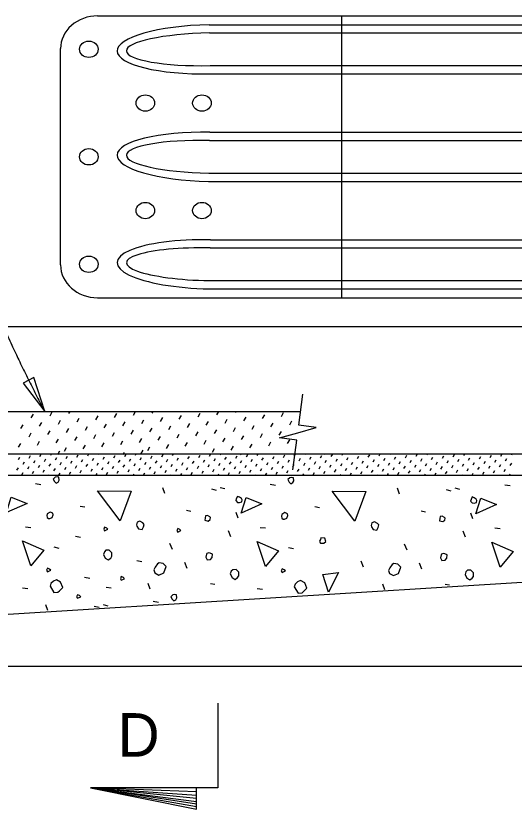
# Model space of a CAD drawing. Extents: x 1.5 to 68.7, y 0 to 31.1.
# Drawn here: x 28.438 to 31.375, y 8.892 to 13.565 of the extents above; entities that cross this region are included whole.
import ezdxf

# ---------------------------------------------------------------- set-up
doc = ezdxf.new("R2010")
doc.units = 0
for name, color, linetype in [('AdhocPoint_dp', 7, 'Continuous'), ('Border', 7, 'Continuous'), ('Patterning', 7, 'Continuous'), ('PlotBorder_dp', 7, 'Continuous'), ('SheetBorder_dp', 7, 'Continuous')]:
    doc.layers.add(name, color=color, linetype=linetype)

msp = doc.modelspace()

# ---------------------------------------------------------------- linework, layer by layer
at = {"layer": 'AdhocPoint_dp'}
for p, q in [((29.503, 8.9937), (28.878, 9.0171)), ((28.878, 9.0171), (29.503, 8.9737)), ((29.503, 8.9554), (28.878, 9.0171)), ((28.878, 9.0171), (29.503, 8.9371)), ((29.503, 8.9204), (28.878, 9.0171)), ((28.878, 9.0171), (29.503, 8.9071))]:
    msp.add_line(p, q, dxfattribs=at)
msp.add_lwpolyline([(28.6078, 11.2336), (28.5427, 11.4345), (28.4801, 11.4019)], close=True, dxfattribs=at)
for points in [[(30.0701, 10.8911), (30.0933, 11.0649), (29.9908, 11.0786), (30.0992, 11.1095), (30.2076, 11.1405), (30.1052, 11.1541), (30.1295, 11.3365)], [(29.628, 9.5171), (29.628, 9.0171), (28.878, 9.0171), (29.503, 8.8921), (29.503, 9.0171)]]:
    msp.add_lwpolyline(points, dxfattribs=at)
msp.add_open_spline([(25.4341, 13.3896), (27.814, 13.1117), (28.2987, 11.8257), (28.6078, 11.2336)], degree=2, dxfattribs=at)
at = {"layer": 'Border'}
for centre in [(28.8677, 13.3677), (29.201, 13.0511), (29.5344, 13.0511), (28.8677, 12.7345), (29.201, 12.418), (29.5344, 12.418), (28.8677, 12.1013)]:
    msp.add_ellipse(centre, major_axis=(0.0547, 0), ratio=0.882613, dxfattribs=at)
at = {"layer": 'Patterning'}
for p, q in [((28.9195, 13.5645), (37.6978, 13.5645)), ((30.3588, 11.9044), (30.3588, 13.5645)), ((29.5771, 13.5123), (37.6978, 13.5123)), ((29.5783, 13.4641), (37.6978, 13.4641)), ((28.7009, 12.0972), (28.7009, 13.3717)), ((29.5831, 13.2713), (37.6978, 13.2713)), ((29.5842, 13.2231), (37.6978, 13.2231)), ((29.5807, 12.8791), (37.6978, 12.8791)), ((29.5795, 12.8309), (37.6978, 12.8309)), ((29.5747, 12.6381), (37.6978, 12.6381)), ((29.5735, 12.5899), (37.6978, 12.5899)), ((29.5842, 12.246), (37.6978, 12.246)), ((29.5831, 12.1978), (37.6978, 12.1978)), ((29.5783, 12.0049), (37.6978, 12.0049)), ((29.5771, 11.9567), (37.6978, 11.9567)), ((28.9195, 11.9044), (37.6978, 11.9044)), ((28.5285, 11.1961), (28.5415, 11.2184)), ((28.6392, 11.209), (28.6521, 11.2314)), ((28.7498, 11.222), (28.757, 11.2345)), ((29.0199, 11.1991), (29.0329, 11.2215)), ((29.1305, 11.212), (29.1435, 11.2344)), ((29.2412, 11.225), (29.2467, 11.2345)), ((29.5113, 11.2021), (29.5242, 11.2245)), ((29.6219, 11.2151), (29.6332, 11.2345)), ((29.7325, 11.228), (29.7363, 11.2345)), ((29.892, 11.1921), (29.905, 11.2145)), ((30.0026, 11.2051), (30.0156, 11.2275)), ((28.5774, 11.1472), (28.5903, 11.1696)), ((28.688, 11.1602), (28.701, 11.1826)), ((28.7986, 11.1731), (28.8116, 11.1955)), ((28.9093, 11.1861), (28.9222, 11.2085)), ((29.0687, 11.1502), (29.0817, 11.1726)), ((29.1794, 11.1632), (29.1923, 11.1856)), ((29.29, 11.1762), (29.303, 11.1986)), ((29.4006, 11.1891), (29.4136, 11.2115)), ((29.5601, 11.1533), (29.5731, 11.1756)), ((29.6707, 11.1662), (29.6837, 11.1886)), ((29.7814, 11.1792), (29.7943, 11.2016)), ((30.0515, 11.1563), (30.0644, 11.1787)), ((28.4667, 11.1343), (28.4797, 11.1566)), ((28.6262, 11.0984), (28.6392, 11.1208)), ((28.7368, 11.1113), (28.7498, 11.1337)), ((28.8475, 11.1243), (28.8604, 11.1467)), ((28.9581, 11.1373), (28.9711, 11.1597)), ((29.1176, 11.1014), (29.1305, 11.1238)), ((29.2282, 11.1144), (29.2412, 11.1368)), ((29.3388, 11.1273), (29.3518, 11.1497)), ((29.4495, 11.1403), (29.4624, 11.1627)), ((29.6089, 11.1044), (29.6219, 11.1268)), ((29.7196, 11.1174), (29.7325, 11.1398)), ((29.8302, 11.1304), (29.8432, 11.1527)), ((29.9408, 11.1433), (29.9538, 11.1657)), ((28.5156, 11.0854), (28.5285, 11.1078)), ((28.7857, 11.0625), (28.7986, 11.0849)), ((28.8963, 11.0755), (28.9093, 11.0979)), ((29.0069, 11.0884), (29.0199, 11.1108)), ((29.1664, 11.0526), (29.1794, 11.075)), ((29.277, 11.0655), (29.29, 11.0879)), ((29.3877, 11.0785), (29.4006, 11.1009)), ((29.4983, 11.0915), (29.5113, 11.1139)), ((29.6578, 11.0556), (29.6707, 11.078)), ((29.7684, 11.0686), (29.7814, 11.0909)), ((29.879, 11.0815), (29.892, 11.1039)), ((29.9897, 11.0945), (30.0026, 11.1169)), ((28.4538, 11.0236), (28.4667, 11.046)), ((28.5644, 11.0366), (28.5774, 11.059)), ((28.675, 11.0495), (28.688, 11.0719)), ((28.8345, 11.0137), (28.8475, 11.0361)), ((28.9451, 11.0266), (28.9581, 11.049)), ((29.0558, 11.0396), (29.0687, 11.062)), ((29.3259, 11.0167), (29.3388, 11.0391)), ((29.4365, 11.0297), (29.4495, 11.0521)), ((29.5471, 11.0426), (29.5601, 11.065)), ((29.7066, 11.0068), (29.7196, 11.0291)), ((29.8172, 11.0197), (29.8302, 11.0421)), ((29.9279, 11.0327), (29.9408, 11.0551)), ((30.0385, 11.0456), (30.0515, 11.068)), ((28.5793, 10.9683), (28.5874, 10.9823)), ((28.6428, 10.9764), (28.6474, 10.9845)), ((28.6841, 10.9816), (28.6966, 11.0032)), ((28.7239, 11.0007), (28.7368, 11.0231)), ((28.8609, 10.973), (28.8675, 10.9845)), ((28.9244, 10.9811), (28.9264, 10.9845)), ((29.0706, 10.9816), (29.0774, 10.9933)), ((29.0791, 10.9697), (29.0872, 10.9836)), ((29.1426, 10.9778), (29.1465, 10.9845)), ((29.175, 10.9838), (29.188, 11.0062)), ((29.2152, 11.0037), (29.2282, 11.0261)), ((29.3608, 10.9744), (29.3666, 10.9845)), ((29.4243, 10.9825), (29.4254, 10.9845)), ((29.5789, 10.971), (29.5868, 10.9845)), ((29.596, 10.9938), (29.6089, 11.0162)), ((29.6424, 10.9791), (29.6456, 10.9845)), ((29.7624, 10.9788), (29.7657, 10.9845)), ((29.7971, 10.9676), (29.8052, 10.9816)), ((29.8606, 10.9757), (29.8657, 10.9845)), ((29.9241, 10.9838), (29.9245, 10.9845)), ((30.0788, 10.9723), (30.0858, 10.9845)), ((30.1423, 10.9804), (30.1446, 10.9845)), ((30.2538, 10.9818), (30.2554, 10.9845)), ((30.2969, 10.9689), (30.305, 10.9829)), ((30.3604, 10.977), (30.3648, 10.9845)), ((30.5786, 10.9736), (30.5849, 10.9845)), ((30.6421, 10.9817), (30.6437, 10.9845)), ((30.7968, 10.9702), (30.8049, 10.9842)), ((30.8603, 10.9783), (30.8638, 10.9845)), ((31.0149, 10.9669), (31.0231, 10.9808)), ((31.0784, 10.975), (31.084, 10.9845)), ((31.1419, 10.9831), (31.1428, 10.9845)), ((31.2966, 10.9716), (31.3041, 10.9845)), ((31.3601, 10.9797), (31.3629, 10.9845)), ((28.4523, 10.9521), (28.4604, 10.9661)), ((28.48, 10.9244), (28.4881, 10.9384)), ((28.5158, 10.9602), (28.5239, 10.9742)), ((28.5435, 10.9325), (28.5516, 10.9465)), ((28.607, 10.9406), (28.6151, 10.9546)), ((28.6704, 10.9487), (28.6786, 10.9627)), ((28.6981, 10.921), (28.7062, 10.935)), ((28.7339, 10.9568), (28.742, 10.9708)), ((28.7616, 10.9291), (28.7697, 10.9431)), ((28.7974, 10.9649), (28.8055, 10.9789)), ((28.8251, 10.9372), (28.8332, 10.9512)), ((28.8886, 10.9453), (28.8967, 10.9593)), ((28.9521, 10.9534), (28.9602, 10.9674)), ((28.9798, 10.9258), (28.9879, 10.9397)), ((29.0156, 10.9616), (29.0237, 10.9755)), ((29.0433, 10.9339), (29.0514, 10.9479)), ((29.1068, 10.942), (29.1149, 10.956)), ((29.1703, 10.9501), (29.1784, 10.9641)), ((29.198, 10.9224), (29.2061, 10.9364)), ((29.2338, 10.9582), (29.2419, 10.9722)), ((29.2615, 10.9305), (29.2696, 10.9445)), ((29.2973, 10.9663), (29.3054, 10.9803)), ((29.325, 10.9386), (29.3331, 10.9526)), ((29.3885, 10.9467), (29.3966, 10.9607)), ((29.4519, 10.9548), (29.4601, 10.9688)), ((29.4796, 10.9271), (29.4877, 10.9411)), ((29.5154, 10.9629), (29.5235, 10.9769)), ((29.5431, 10.9352), (29.5512, 10.9492)), ((29.6066, 10.9433), (29.6147, 10.9573)), ((29.6701, 10.9514), (29.6782, 10.9654)), ((29.6978, 10.9237), (29.7059, 10.9377)), ((29.7336, 10.9595), (29.7417, 10.9735)), ((29.7613, 10.9318), (29.7694, 10.9458)), ((29.8248, 10.9399), (29.8329, 10.9539)), ((29.8883, 10.948), (29.8964, 10.962)), ((29.916, 10.9203), (29.9241, 10.9343)), ((29.9518, 10.9561), (29.9599, 10.9701)), ((29.9795, 10.9284), (29.9876, 10.9424)), ((30.0153, 10.9642), (30.0234, 10.9782)), ((30.043, 10.9365), (30.0511, 10.9505)), ((30.1065, 10.9446), (30.1146, 10.9586)), ((30.17, 10.9527), (30.1781, 10.9667)), ((30.1977, 10.925), (30.2058, 10.939)), ((30.2334, 10.9608), (30.2416, 10.9748)), ((30.2611, 10.9331), (30.2692, 10.9471)), ((30.3246, 10.9412), (30.3327, 10.9552)), ((30.3881, 10.9493), (30.3962, 10.9633)), ((30.4158, 10.9216), (30.4239, 10.9356)), ((30.4516, 10.9574), (30.4597, 10.9714)), ((30.4793, 10.9297), (30.4874, 10.9437)), ((30.5151, 10.9655), (30.5232, 10.9795)), ((30.5428, 10.9378), (30.5509, 10.9518)), ((30.6063, 10.9459), (30.6144, 10.9599)), ((30.6698, 10.954), (30.6779, 10.968)), ((30.6975, 10.9263), (30.7056, 10.9403)), ((30.7333, 10.9621), (30.7414, 10.9761)), ((30.761, 10.9344), (30.7691, 10.9484)), ((30.8245, 10.9425), (30.8326, 10.9565)), ((30.888, 10.9506), (30.8961, 10.9646)), ((30.9157, 10.923), (30.9238, 10.9369)), ((30.9515, 10.9588), (30.9596, 10.9727)), ((30.9792, 10.9311), (30.9873, 10.9451)), ((31.0426, 10.9392), (31.0507, 10.9532)), ((31.1061, 10.9473), (31.1142, 10.9613)), ((31.1696, 10.9554), (31.1777, 10.9694)), ((31.1973, 10.9277), (31.2054, 10.9417)), ((31.2331, 10.9635), (31.2412, 10.9775)), ((31.2608, 10.9358), (31.2689, 10.9498)), ((31.3243, 10.9439), (31.3324, 10.9579)), ((28.4442, 10.8886), (28.4523, 10.9026)), ((28.5077, 10.8967), (28.5158, 10.9107)), ((28.5712, 10.9048), (28.5793, 10.9188)), ((28.5989, 10.8771), (28.607, 10.8911)), ((28.6347, 10.9129), (28.6428, 10.9269)), ((28.6623, 10.8852), (28.6704, 10.8992)), ((28.7258, 10.8933), (28.7339, 10.9073)), ((28.7893, 10.9014), (28.7974, 10.9154)), ((28.817, 10.8738), (28.8251, 10.8877)), ((28.8528, 10.9095), (28.8609, 10.9235)), ((28.8805, 10.8819), (28.8886, 10.8958)), ((28.9163, 10.9177), (28.9244, 10.9316)), ((28.944, 10.89), (28.9521, 10.904)), ((29.0075, 10.8981), (29.0156, 10.9121)), ((29.071, 10.9062), (29.0791, 10.9202)), ((29.0987, 10.8785), (29.1068, 10.8925)), ((29.1345, 10.9143), (29.1426, 10.9283)), ((29.1622, 10.8866), (29.1703, 10.9006)), ((29.2257, 10.8947), (29.2338, 10.9087)), ((29.2892, 10.9028), (29.2973, 10.9168)), ((29.3169, 10.8751), (29.325, 10.8891)), ((29.3527, 10.9109), (29.3608, 10.9249)), ((29.3804, 10.8832), (29.3885, 10.8972)), ((29.4162, 10.919), (29.4243, 10.933)), ((29.4438, 10.8913), (29.4519, 10.9053)), ((29.5073, 10.8994), (29.5154, 10.9134)), ((29.5708, 10.9075), (29.5789, 10.9215)), ((29.5985, 10.8798), (29.6066, 10.8938)), ((29.6343, 10.9156), (29.6424, 10.9296)), ((29.662, 10.8879), (29.6701, 10.9019)), ((29.7255, 10.896), (29.7336, 10.91)), ((29.789, 10.9041), (29.7971, 10.9181)), ((29.8167, 10.8764), (29.8248, 10.8904)), ((29.8525, 10.9122), (29.8606, 10.9262)), ((29.8802, 10.8845), (29.8883, 10.8985)), ((29.9437, 10.8926), (29.9518, 10.9066)), ((30.0072, 10.9007), (30.0153, 10.9147)), ((30.0707, 10.9088), (30.0788, 10.9228)), ((30.0984, 10.8811), (30.1065, 10.8951)), ((30.1342, 10.9169), (30.1423, 10.9309)), ((30.1619, 10.8892), (30.17, 10.9032)), ((30.2253, 10.8973), (30.2334, 10.9113)), ((30.2888, 10.9054), (30.2969, 10.9194)), ((30.3165, 10.8777), (30.3246, 10.8917)), ((30.3523, 10.9135), (30.3604, 10.9275)), ((30.38, 10.8858), (30.3881, 10.8998)), ((30.4435, 10.8939), (30.4516, 10.9079)), ((30.507, 10.902), (30.5151, 10.916)), ((30.5347, 10.8743), (30.5428, 10.8883)), ((30.5705, 10.9101), (30.5786, 10.9241)), ((30.5982, 10.8824), (30.6063, 10.8964)), ((30.634, 10.9182), (30.6421, 10.9322)), ((30.6617, 10.8905), (30.6698, 10.9045)), ((30.7252, 10.8986), (30.7333, 10.9126)), ((30.7887, 10.9067), (30.7968, 10.9207)), ((30.8164, 10.8791), (30.8245, 10.893)), ((30.8522, 10.9149), (30.8603, 10.9288)), ((30.8799, 10.8872), (30.888, 10.9012)), ((30.9434, 10.8953), (30.9515, 10.9093)), ((31.0068, 10.9034), (31.0149, 10.9174)), ((31.0345, 10.8757), (31.0426, 10.8897)), ((31.0703, 10.9115), (31.0784, 10.9255)), ((31.098, 10.8838), (31.1061, 10.8978)), ((31.1338, 10.9196), (31.1419, 10.9336)), ((31.1615, 10.8919), (31.1696, 10.9059)), ((31.225, 10.9), (31.2331, 10.914)), ((31.2885, 10.9081), (31.2966, 10.9221)), ((31.3162, 10.8804), (31.3243, 10.8944)), ((31.352, 10.9162), (31.3601, 10.9302)), ((28.4719, 10.8609), (28.48, 10.8749)), ((28.5354, 10.869), (28.5435, 10.883)), ((28.6324, 10.8595), (28.6347, 10.8634)), ((28.6912, 10.8595), (28.6981, 10.8715)), ((28.7535, 10.8656), (28.7616, 10.8796)), ((28.8525, 10.8595), (28.8528, 10.8601)), ((28.9113, 10.8595), (28.9163, 10.8682)), ((28.9717, 10.8623), (28.9798, 10.8763)), ((29.0352, 10.8704), (29.0433, 10.8844)), ((29.1314, 10.8595), (29.1345, 10.8648)), ((29.1902, 10.8595), (29.198, 10.8729)), ((29.2534, 10.867), (29.2615, 10.881)), ((29.3516, 10.8595), (29.3527, 10.8614)), ((29.4104, 10.8595), (29.4162, 10.8695)), ((29.4715, 10.8636), (29.4796, 10.8776)), ((29.535, 10.8717), (29.5431, 10.8857)), ((29.6305, 10.8595), (29.6343, 10.8661)), ((29.6897, 10.8602), (29.6978, 10.8742)), ((29.7532, 10.8683), (29.7613, 10.8823)), ((29.8506, 10.8595), (29.8525, 10.8627)), ((29.9094, 10.8595), (29.916, 10.8708)), ((29.9714, 10.8649), (29.9795, 10.8789)), ((30.0349, 10.873), (30.043, 10.887)), ((30.1296, 10.8595), (30.1342, 10.8674)), ((30.1895, 10.8615), (30.1977, 10.8755)), ((30.253, 10.8696), (30.2611, 10.8836)), ((30.3497, 10.8595), (30.3523, 10.864)), ((30.4085, 10.8595), (30.4158, 10.8721)), ((30.4712, 10.8662), (30.4793, 10.8802)), ((30.5698, 10.8595), (30.5705, 10.8606)), ((30.6286, 10.8595), (30.634, 10.8687)), ((30.6894, 10.8629), (30.6975, 10.8768)), ((30.7529, 10.871), (30.761, 10.8849)), ((30.8488, 10.8595), (30.8522, 10.8654)), ((30.9076, 10.8595), (30.9157, 10.8735)), ((30.971, 10.8676), (30.9792, 10.8816)), ((31.0689, 10.8595), (31.0703, 10.862)), ((31.1277, 10.8595), (31.1338, 10.8701)), ((31.1892, 10.8642), (31.1973, 10.8782)), ((31.2527, 10.8723), (31.2608, 10.8863)), ((31.3478, 10.8595), (31.352, 10.8667)), ((28.554, 10.81), (28.5841, 10.8047)), ((29.9373, 10.8065), (29.9673, 10.8012)), ((31.3206, 10.8029), (31.3506, 10.7976)), ((29.3159, 10.7517), (29.3035, 10.7852)), ((29.5899, 10.7782), (29.6182, 10.7711)), ((29.6416, 10.7875), (29.6699, 10.7804)), ((30.6992, 10.7481), (30.6868, 10.7817)), ((30.9732, 10.7746), (31.0015, 10.7676)), ((31.0249, 10.7839), (31.0532, 10.7768)), ((28.8174, 10.6774), (28.8439, 10.6721)), ((30.2007, 10.6739), (30.2272, 10.6686)), ((29.4432, 10.6527), (29.4697, 10.6474)), ((29.7477, 10.6063), (29.7353, 10.6398)), ((30.8265, 10.6491), (30.853, 10.6438)), ((31.131, 10.6027), (31.1186, 10.6363)), ((28.4939, 10.5554), (28.5257, 10.5519)), ((29.7053, 10.4967), (29.6911, 10.532)), ((29.8772, 10.5519), (29.909, 10.5484)), ((31.0885, 10.4931), (31.0744, 10.5285)), ((31.2605, 10.5484), (31.2923, 10.5448)), ((28.7893, 10.4998), (28.8194, 10.4945)), ((28.6618, 10.437), (28.6901, 10.4299)), ((29.3601, 10.4211), (29.346, 10.4564)), ((30.0451, 10.4335), (30.0734, 10.4264)), ((30.7434, 10.4175), (30.7292, 10.4529)), ((29.1503, 10.3562), (29.1803, 10.3509)), ((29.4472, 10.3093), (29.433, 10.3446)), ((30.4871, 10.3168), (30.4729, 10.3521)), ((30.8304, 10.3057), (30.8163, 10.3411)), ((28.8426, 10.2577), (28.8727, 10.2524)), ((28.4775, 10.1961), (28.5076, 10.1908)), ((28.9698, 10.2002), (28.9998, 10.1949)), ((29.2293, 10.1877), (29.2169, 10.2213)), ((29.585, 10.2209), (29.6098, 10.2173)), ((29.8608, 10.1926), (29.8909, 10.1873)), ((30.6126, 10.1842), (30.6002, 10.2178)), ((30.9683, 10.2173), (30.9931, 10.2138)), ((28.626, 10.0618), (28.6137, 10.0954)), ((28.9517, 10.0976), (28.98, 10.0905)), ((29.2474, 10.1166), (29.2775, 10.1113)), ((28.9, 10.0883), (28.9283, 10.0812))]:
    msp.add_line(p, q, dxfattribs=at)
for points in [[(28.6654, 10.8224), (28.676, 10.8118), (28.6866, 10.8188), (28.6937, 10.8294), (28.6901, 10.8471), (28.6813, 10.8489), (28.6689, 10.8471), (28.6583, 10.8365), (28.6654, 10.8224)], [(30.0486, 10.8188), (30.0593, 10.8082), (30.0699, 10.8153), (30.0769, 10.8259), (30.0734, 10.8436), (30.0646, 10.8453), (30.0522, 10.8436), (30.0416, 10.833), (30.0486, 10.8188)], [(29.0525, 10.5908), (28.9182, 10.7676), (29.1179, 10.7658), (29.0525, 10.5908)], [(30.4358, 10.5873), (30.3014, 10.764), (30.5012, 10.7623), (30.4358, 10.5873)], [(28.3825, 10.6385), (28.4108, 10.7304), (28.5045, 10.6933), (28.3825, 10.6385)], [(29.7441, 10.6991), (29.7565, 10.6973), (29.7689, 10.7026), (29.7724, 10.7132), (29.7671, 10.722), (29.7565, 10.7291), (29.7441, 10.7344), (29.7371, 10.7203), (29.7335, 10.7097), (29.7441, 10.6991)], [(29.7658, 10.635), (29.7941, 10.7269), (29.8878, 10.6898), (29.7658, 10.635)], [(31.1274, 10.6955), (31.1398, 10.6938), (31.1522, 10.6991), (31.1557, 10.7097), (31.1504, 10.7185), (31.1398, 10.7256), (31.1274, 10.7309), (31.1204, 10.7167), (31.1168, 10.7061), (31.1274, 10.6955)], [(31.1491, 10.6314), (31.1774, 10.7234), (31.2711, 10.6862), (31.1491, 10.6314)], [(28.63, 10.6032), (28.6371, 10.6032), (28.6512, 10.6102), (28.6565, 10.6261), (28.6548, 10.635), (28.6406, 10.6421), (28.6229, 10.6314), (28.6194, 10.6208), (28.6229, 10.6102), (28.63, 10.6032)], [(29.551, 10.5943), (29.5705, 10.589), (29.5828, 10.5979), (29.5846, 10.6102), (29.5811, 10.6138), (29.5669, 10.6208), (29.5546, 10.6191), (29.5528, 10.6067), (29.551, 10.5943)], [(30.0133, 10.5996), (30.0204, 10.5996), (30.0345, 10.6067), (30.0398, 10.6226), (30.038, 10.6314), (30.0239, 10.6385), (30.0062, 10.6279), (30.0027, 10.6173), (30.0062, 10.6067), (30.0133, 10.5996)], [(30.9343, 10.5908), (30.9537, 10.5855), (30.9661, 10.5943), (30.9679, 10.6067), (30.9643, 10.6102), (30.9502, 10.6173), (30.9378, 10.6155), (30.9361, 10.6032), (30.9343, 10.5908)], [(29.1515, 10.559), (29.1603, 10.5431), (29.1816, 10.5395), (29.1904, 10.5554), (29.1939, 10.5696), (29.1851, 10.5784), (29.1692, 10.5873), (29.1533, 10.582), (29.148, 10.566), (29.1515, 10.559)], [(30.5348, 10.5554), (30.5436, 10.5395), (30.5648, 10.536), (30.5737, 10.5519), (30.5772, 10.566), (30.5684, 10.5749), (30.5525, 10.5837), (30.5366, 10.5784), (30.5312, 10.5625), (30.5348, 10.5554)], [(28.9606, 10.532), (28.9801, 10.5408), (28.973, 10.5479), (28.9606, 10.5532), (28.9553, 10.5408), (28.9606, 10.532)], [(29.3914, 10.5238), (29.4108, 10.5326), (29.4037, 10.5397), (29.3914, 10.545), (29.3861, 10.5326), (29.3914, 10.5238)], [(28.5253, 10.3252), (28.4775, 10.4719), (28.6031, 10.4171), (28.5253, 10.3252)], [(29.9086, 10.3216), (29.8608, 10.4684), (29.9863, 10.4136), (29.9086, 10.3216)], [(30.2325, 10.4582), (30.2537, 10.4582), (30.2643, 10.4688), (30.259, 10.4883), (30.236, 10.49), (30.2325, 10.4794), (30.2272, 10.4706), (30.2325, 10.4582), (30.229, 10.4617)], [(31.2918, 10.3181), (31.2441, 10.4648), (31.3696, 10.41), (31.2918, 10.3181)], [(28.9543, 10.3918), (28.9649, 10.3706), (28.9826, 10.36), (28.9967, 10.3706), (29.0038, 10.3812), (29.0038, 10.4024), (28.9879, 10.4183), (28.9684, 10.4165), (28.9596, 10.4077), (28.9543, 10.3918)], [(29.5568, 10.3764), (29.5656, 10.3605), (29.585, 10.3623), (29.5939, 10.3747), (29.5957, 10.3941), (29.5833, 10.3994), (29.5744, 10.4012), (29.5638, 10.3977), (29.5603, 10.3941), (29.5568, 10.3764)], [(30.94, 10.3729), (30.9489, 10.357), (30.9683, 10.3588), (30.9772, 10.3711), (30.9789, 10.3906), (30.9666, 10.3959), (30.9577, 10.3977), (30.9471, 10.3941), (30.9436, 10.3906), (30.94, 10.3729)], [(29.2576, 10.2832), (29.2806, 10.2708), (29.3106, 10.2832), (29.323, 10.3203), (29.3053, 10.338), (29.2823, 10.3433), (29.2717, 10.3362), (29.2593, 10.3168), (29.2505, 10.3009), (29.2576, 10.2832)], [(30.6408, 10.2797), (30.6638, 10.2673), (30.6939, 10.2797), (30.7063, 10.3168), (30.6886, 10.3345), (30.6656, 10.3398), (30.655, 10.3327), (30.6426, 10.3132), (30.6338, 10.2973), (30.6408, 10.2797)], [(28.6243, 10.2898), (28.6437, 10.2987), (28.6366, 10.3057), (28.6243, 10.311), (28.619, 10.2987), (28.6243, 10.2898)], [(29.7017, 10.2775), (29.7123, 10.2562), (29.73, 10.2456), (29.7441, 10.2562), (29.7512, 10.2668), (29.7512, 10.2881), (29.7353, 10.304), (29.7159, 10.3022), (29.707, 10.2934), (29.7017, 10.2775)], [(30.0075, 10.2863), (30.027, 10.2951), (30.0199, 10.3022), (30.0075, 10.3075), (30.0022, 10.2951), (30.0075, 10.2863)], [(30.2802, 10.1701), (30.2466, 10.2744), (30.3403, 10.2867), (30.2802, 10.1701)], [(31.085, 10.2739), (31.0956, 10.2527), (31.1133, 10.2421), (31.1274, 10.2527), (31.1345, 10.2633), (31.1345, 10.2845), (31.1186, 10.3004), (31.0991, 10.2987), (31.0903, 10.2898), (31.085, 10.2739)], [(28.6393, 10.205), (28.6623, 10.1679), (28.6852, 10.1696), (28.6941, 10.1785), (28.7135, 10.1979), (28.7012, 10.228), (28.6764, 10.2421), (28.6587, 10.235), (28.6446, 10.2209), (28.6393, 10.205)], [(29.0591, 10.2406), (29.0785, 10.2494), (29.0715, 10.2565), (29.0591, 10.2618), (29.0538, 10.2494), (29.0591, 10.2406)], [(30.0783, 10.2014), (30.1012, 10.1643), (30.1242, 10.1661), (30.1331, 10.1749), (30.1525, 10.1944), (30.1401, 10.2244), (30.1154, 10.2386), (30.0977, 10.2315), (30.0836, 10.2173), (30.0783, 10.2014)], [(28.8007, 10.1339), (28.8201, 10.1427), (28.813, 10.1498), (28.8007, 10.1551), (28.7954, 10.1427), (28.8007, 10.1339)], [(29.3588, 10.129), (29.3694, 10.1184), (29.38, 10.1254), (29.3871, 10.136), (29.3835, 10.1537), (29.3747, 10.1555), (29.3623, 10.1537), (29.3517, 10.1431), (29.3588, 10.129)]]:
    msp.add_lwpolyline(points, dxfattribs=at)
for centre, major_axis, ratio, start_param, end_param in [((28.9195, 13.3718), (0.2185, 0), 0.882613, 1.570796, 3.141593), ((29.5807, 13.3677), (-0.5464, -0.0102), 0.264749, 4.713933, 7.855525), ((29.5807, 13.3677), (-0.4917, -0.0093), 0.196063, 4.713495, 7.855087), ((29.5771, 12.7345), (-0.5428, 0.0103), 0.266477, 4.71081, 7.852402), ((29.5771, 12.7345), (-0.4882, 0.0094), 0.197486, 4.711258, 7.85285), ((29.5807, 12.1013), (-0.5464, 0.0102), 0.264749, 4.710845, 7.852438), ((29.5807, 12.1013), (-0.4917, 0.0093), 0.196063, 4.711283, 7.852876), ((28.9195, 12.0973), (0.2185, 0), 0.882613, 3.141593, 4.712389)]:
    msp.add_ellipse(centre, major_axis=major_axis, ratio=ratio, start_param=start_param, end_param=end_param, dxfattribs=at)
at = {"layer": 'PlotBorder_dp'}
for p, q in [((26.2771, 11.7345), (36.6763, 11.7345)), ((27.8541, 11.2345), (30.1159, 11.2345)), ((27.4971, 10.9845), (37.6978, 10.9845)), ((28.2772, 10.8595), (34.2217, 10.8595)), ((27.4971, 9.9844), (31.4971, 10.2344)), ((27.4971, 9.7345), (36.6763, 9.7345))]:
    msp.add_line(p, q, dxfattribs=at)

# ---------------------------------------------------------------- texts
at = {"layer": 'SheetBorder_dp'}
msp.add_text('D', height=0.256, dxfattribs=at).set_placement((29.0376, 9.2014))

doc.saveas('drawing.dxf')
